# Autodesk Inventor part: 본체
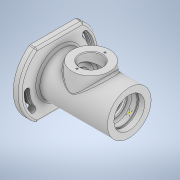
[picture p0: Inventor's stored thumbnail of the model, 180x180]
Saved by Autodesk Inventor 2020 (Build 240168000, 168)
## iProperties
Created: 2022-05
Part Number: 본체
Material: 일반
Document SubType Name: Modeling
Designer: Student
Density: 1 g/cm^3
Appearance: 기본값
Author: Student
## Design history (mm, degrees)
sketch "스케치1"
  geometry: L1 (65.838, 0)-(-65.838, 0); L2 (56, 32)-(-46, 32); L3 (-23.801, 32)-(-46, 32); L4 (-46, 32)-(-46, 58); L5 (-46, 58)-(-56, 58); L6 (-56, 58)-(-56, 36); L7 (-56, 36)-(-59, 36); L8 (-59, 36)-(-59, 30); L9 (-59, 30)-(-45, 20); L10 (-45, 20)-(-45, 15.19); L11 (-37.7, 14.786)-(-37.7, 11); L12 (-37.7, 11)-(-35, 11); L13 (-35, 11)-(-35, 15); L14 (-35, 15)-(-30, 15); L15 (-30, 15)-(-30, 17.5); L16 (-30, 17.5)-(-19, 17.5); L17 (-19, 17.5)-(-19, 27); L18 (-19, 27)-(19, 27); L19 (19, 27)-(19, 17.5); L20 (34, 17.5)-(34, 22.5); L21 (34, 22.5)-(45, 22.5); L22 (45, 22.5)-(45, 24); L23 (45, 24)-(48, 24); L24 (48, 24)-(48, 22.5); L25 (48, 22.5)-(56, 22.5); L26 (56, 22.5)-(56, 32); L27 (34, 17.5)-(30, 17.5); L28 (28.25, 17.5)-(28.25, 18.5); L29 (28.25, 18.5)-(30, 18.5); L30 (30, 18.5)-(30, 17.5); L31 (28.25, 17.5)-(19, 17.5); L32 (-44.3, 14.786)-(-45, 15.19); L33 (-44.3, 14.786)-(-37.7, 14.786); 2 further points
  constraints: 66 end point, 25 perpendicular, 3 horizontal, 1 coincident, 1 horizontal alignment, 1 midpoint, 1 point on line
  dimensions: "d2" = 102 distance between parallel lines of L4 L26; "d3" = 13 distance between parallel lines of L8 L4; "d4" = 3 distance of L6.end L7.end; "d5" = 64 diameter of L2 L1; "d6" = 48 diameter of L23 L1; "d7" = 45 diameter of L21 L1; "d8" = 54 diameter of L18 L1; "d9" = 30 diameter of L14 L1; "d10" = 22 diameter of L12 L1; "d11" = 40 diameter of L9.end L1; "d12" = 60 diameter of L8.end L1; "d13" = 72 diameter of L7 L1; "d14" = 8 distance of L24.end L25.end; "d15" = 3 distance of L22.end L23.end; "d16" = 22 distance between parallel lines of L20 L26; "d17" = 64 distance between parallel lines of L15 L20; "d18" = 11 distance of L27.end L19.end; "d19" = 38 distance of L17.end L18.end; "d20" = 11 distance between parallel lines of L15 L17; "d21" = 60 distance between parallel lines of L15 L30; "d22" = 5 distance between parallel lines of L13 L15; "d23" = 14 distance between parallel lines of L10 L8; "d24" = 116 diameter of L5 L1; "d26" = 37 diameter of L29 L1; "d28" = 1.75 distance of L28.end L29.end; "d29" = 7.3 distance between parallel lines of L10 L11; "d30" = 35 diameter of L31 L1; "d31" = 19 distance from line of point (0, 0) L19; "d32" = 45 diameter of L25 L1; "d33" = 0.7 distance from line of L32.start L10; "d34" = 30 deg angle of L33 L32
revolve "회전1" sketch "스케치1" stored, may be unused: angle "d35" = 90 deg
sketch "스케치2"
  geometry: L1 (-61.819, 47)-(63.766, 47); L2 (-61.819, -47)-(73.988, -47); C1 r 58 at (0, 0) reference; 5 further points
  constraints: 4 end point, 2 horizontal
  dimensions: "d36" = 47 distance from line of point (0, 0) L1; "d37" = 94 distance between parallel lines of L1 L2
extrude "돌출1" cut sketch "스케치2" distance "d38" = 10; taper "d39" = 0 deg
sketch "스케치5"
  geometry: L1 (0, 0)-(75.323, 0); L2 (0, 0)-(56.239, 47.19); C1 r 32 at (0, 0) reference; C2 r 20 at (0, 0) reference; A1 r 48 centre (0, 0) between (36.77, 30.854) and (-48, 0); A2 r 48 centre (0, 0) between (48, 0) and (36.77, 30.854); A3 r 52 centre (0, 0) between (52, 0) and (39.834, 33.425); A4 r 44 centre (0, 0) between (44, 0) and (33.706, 28.283); A5 r 4 centre (48, 0) between (44, 0) and (52, 0); A6 r 4 centre (36.77, 30.854) between (39.834, 33.425) and (33.706, 28.283); A7 r 48 centre (0, 0) between (-48, 0) and (-38.722, -28.366); A8 r 52 centre (0, 0) between (-52, 0) and (-41.949, -30.73); A9 r 44 centre (0, 0) between (-44, 0) and (-35.495, -26.002); A10 r 4 centre (-48, 0) between (-44, 0) and (-52, 0); A11 r 4 centre (-38.722, -28.366) between (-41.949, -30.73) and (-35.495, -26.002); 1 further point
  constraints: 22 point on circle, 11 centre point, 8 tangent, 4 end point, 3 coincident, 2 concentric, 1 horizontal, 1 point on line
  dimensions: "d51" = 96 diameter of A1; "d52" = 40 deg angle of L1 L2; "d53" = 8 diameter of A5; "d54" = 8 diameter of A11 (derived); "d55" = 48.41661 distance from line of L1.end L2; "d56" = 47.18977 distance from line of L2.end L1; "d57" = 0 distance from line of A3.start L1; "d58" = 26.00217 distance from line of A9.end L1; "d59" = 0 distance from line of A9.start L1
extrude "돌출3" cut sketch "스케치5" distance "d60" = 4.4; taper "d61" = 0 deg
sketch "스케치6"
  geometry: C1 r 4 at (-38.722, -28.366); C2 r 4 at (36.77, 30.854); A1 r 52 centre (0, 0) between (-52, 0) and (-41.949, -30.73) reference; A2 r 4 centre (-38.722, -28.366) between (-41.949, -30.73) and (-35.495, -26.002) reference; A3 r 44 centre (0, 0) between (-44, 0) and (-35.495, -26.002) reference; A4 r 4 centre (-48, 0) between (-44, 0) and (-52, 0) reference; A5 r 4 centre (48, 0) between (44, 0) and (52, 0) reference; A6 r 52 centre (0, 0) between (52, 0) and (39.834, 33.425) reference; A7 r 4 centre (36.77, 30.854) between (39.834, 33.425) and (33.706, 28.283) reference; A8 r 44 centre (0, 0) between (44, 0) and (33.706, 28.283) reference; A9 r 48 centre (0, 0) between (-48, 0) and (-38.722, -28.366); A10 r 50.25 centre (0, 0) between (-50.25, 0) and (-40.537, -29.696); A11 r 45.75 centre (0, 0) between (-45.75, 0) and (-36.907, -27.036); A12 r 2.25 centre (-48, 0) between (-45.75, 0) and (-50.25, 0); A13 r 2.25 centre (-38.722, -28.366) between (-40.537, -29.696) and (-36.907, -27.036); A14 r 48 centre (0, 0) between (48, 0) and (36.77, 30.854); A15 r 50.25 centre (0, 0) between (50.25, 0) and (38.494, 32.3); A16 r 45.75 centre (0, 0) between (45.75, 0) and (35.047, 29.408); A17 r 2.25 centre (48, 0) between (45.75, 0) and (50.25, 0); A18 r 2.25 centre (36.77, 30.854) between (38.494, 32.3) and (35.047, 29.408); 9 further points
  constraints: 20 point on circle, 12 centre point, 8 tangent, 4 coincident
  dimensions: "d62" = 4.5 diameter of A13; "d63" = 4.5 diameter of A17; "d64" = 8 diameter of C1; "d65" = 8 diameter of C2
extrude "돌출4" cut sketch "스케치6" extent not by distance; stored distance "d66" = 4.4; taper "d67" = 0 deg
node "작업 평면1"
sketch "스케치7"
  geometry: C1 r 27.5 at (0, 0); 1 further point
  constraints: 1 centre point, 1 coincident
  dimensions: "d69" = 55 diameter of C1
extrude "돌출5" join sketch "스케치7" stored distance "d70" = 10; taper "d71" = 5 deg
sketch "스케치8"
  geometry: C1 r 16 at (0, 0); 2 further points
  constraints: 1 centre point, 1 coincident, 1 vertical alignment
  dimensions: "d72" = 32 diameter of C1; "d73" = 20.5 distance of point (0, -20.5) point (0, 0)
extrude "돌출6" cut sketch "스케치8" stored distance "d74" = 10; taper "d75" = 0 deg
sketch "스케치9"
  geometry: 3 further points
  constraints: 2 vertical alignment
  dimensions: "d76" = 20.5 distance of point (0, 0) point (0, -20.5); "d84" = 20.5 distance of point (0, 20.5) point (0, 0)
hole "구멍1" sketch "스케치9" at (0, -20.5), (0, 20.5) diameter "d77" = 2.459; stored, may be unused: countersink angle "d81" = 90 deg, drill point angle "d83" = 118 deg; dims "d78" = 6, "d79" = 4, "d80" = 2, "d82" = 8.8
node "작업 평면2"
sketch "스케치10"
  geometry: L1 (-22.847, 8.471)-(34.847, 8.471); L2 (34.847, 8.471)-(34.847, -8.471); L3 (34.847, -8.471)-(-22.847, -8.471); L4 (-22.847, -8.471)-(-22.847, 8.471); L5 (-56, -47)-(-56, 47) reference; 3 further points
  constraints: 2 midpoint, 1 horizontal alignment, 1 parallel, 2 other
  dimensions: "d86" = 62 distance from line of L5 point (6, 8.471); "d87" = 90.84706 distance between parallel lines of L2 L5; "d88" = 16.94192 distance between parallel lines of L3 L1
feature "엠보싱1" sketch "스케치10" dims "d2" = 102, "d3" = 13, "d4" = 3, "d5" = 64, "d6" = 48, "d7" = 45, "d8" = 54, "d9" = 30, "d10" = 22, "d11" = 40, "d12" = 60, "d13" = 72, "d14" = 8, "d15" = 3, "d16" = 22, "d17" = 64, "d18" = 11, "d19" = 38, "d20" = 11, "d21" = 60, "d22" = 5, "d23" = 14, "d24" = 116, "d26" = 37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
fillet "모깎기1" dims "d91" = 3
fillet "모깎기2" dims "d92" = 0.6
fillet "모깎기4" dims "d94" = 0.5
fillet "모깎기5" dims "d95" = 3
chamfer "모따기1" distance "d96" = 1; stored, may be unused: second distance "d97" = 2, angle "d98" = 45 deg
sketch "스케치12"
  geometry: 1 further point
fillet "모깎기6" dims "d99" = 3
chamfer "모따기2" distance "d100" = 1; stored, may be unused: second distance "d101" = 2, angle "d102" = 45 deg
sketch "스케치15"
  geometry: 3 further points
  constraints: 2 coincident
node "솔리드1"
node "투영된 루프1"
node "투영된 루프2"
feature "A9D066F2-1C7D-4E18-AEED-F7BC21143FA4" dims "d77" = 2.459, "d78" = 6, "d79" = 4, "d80" = 2, "d81" = 90 deg, "d82" = 8.8, "d83" = 118 deg
other parameters: "d68" = 38, "d85" = -39.5
